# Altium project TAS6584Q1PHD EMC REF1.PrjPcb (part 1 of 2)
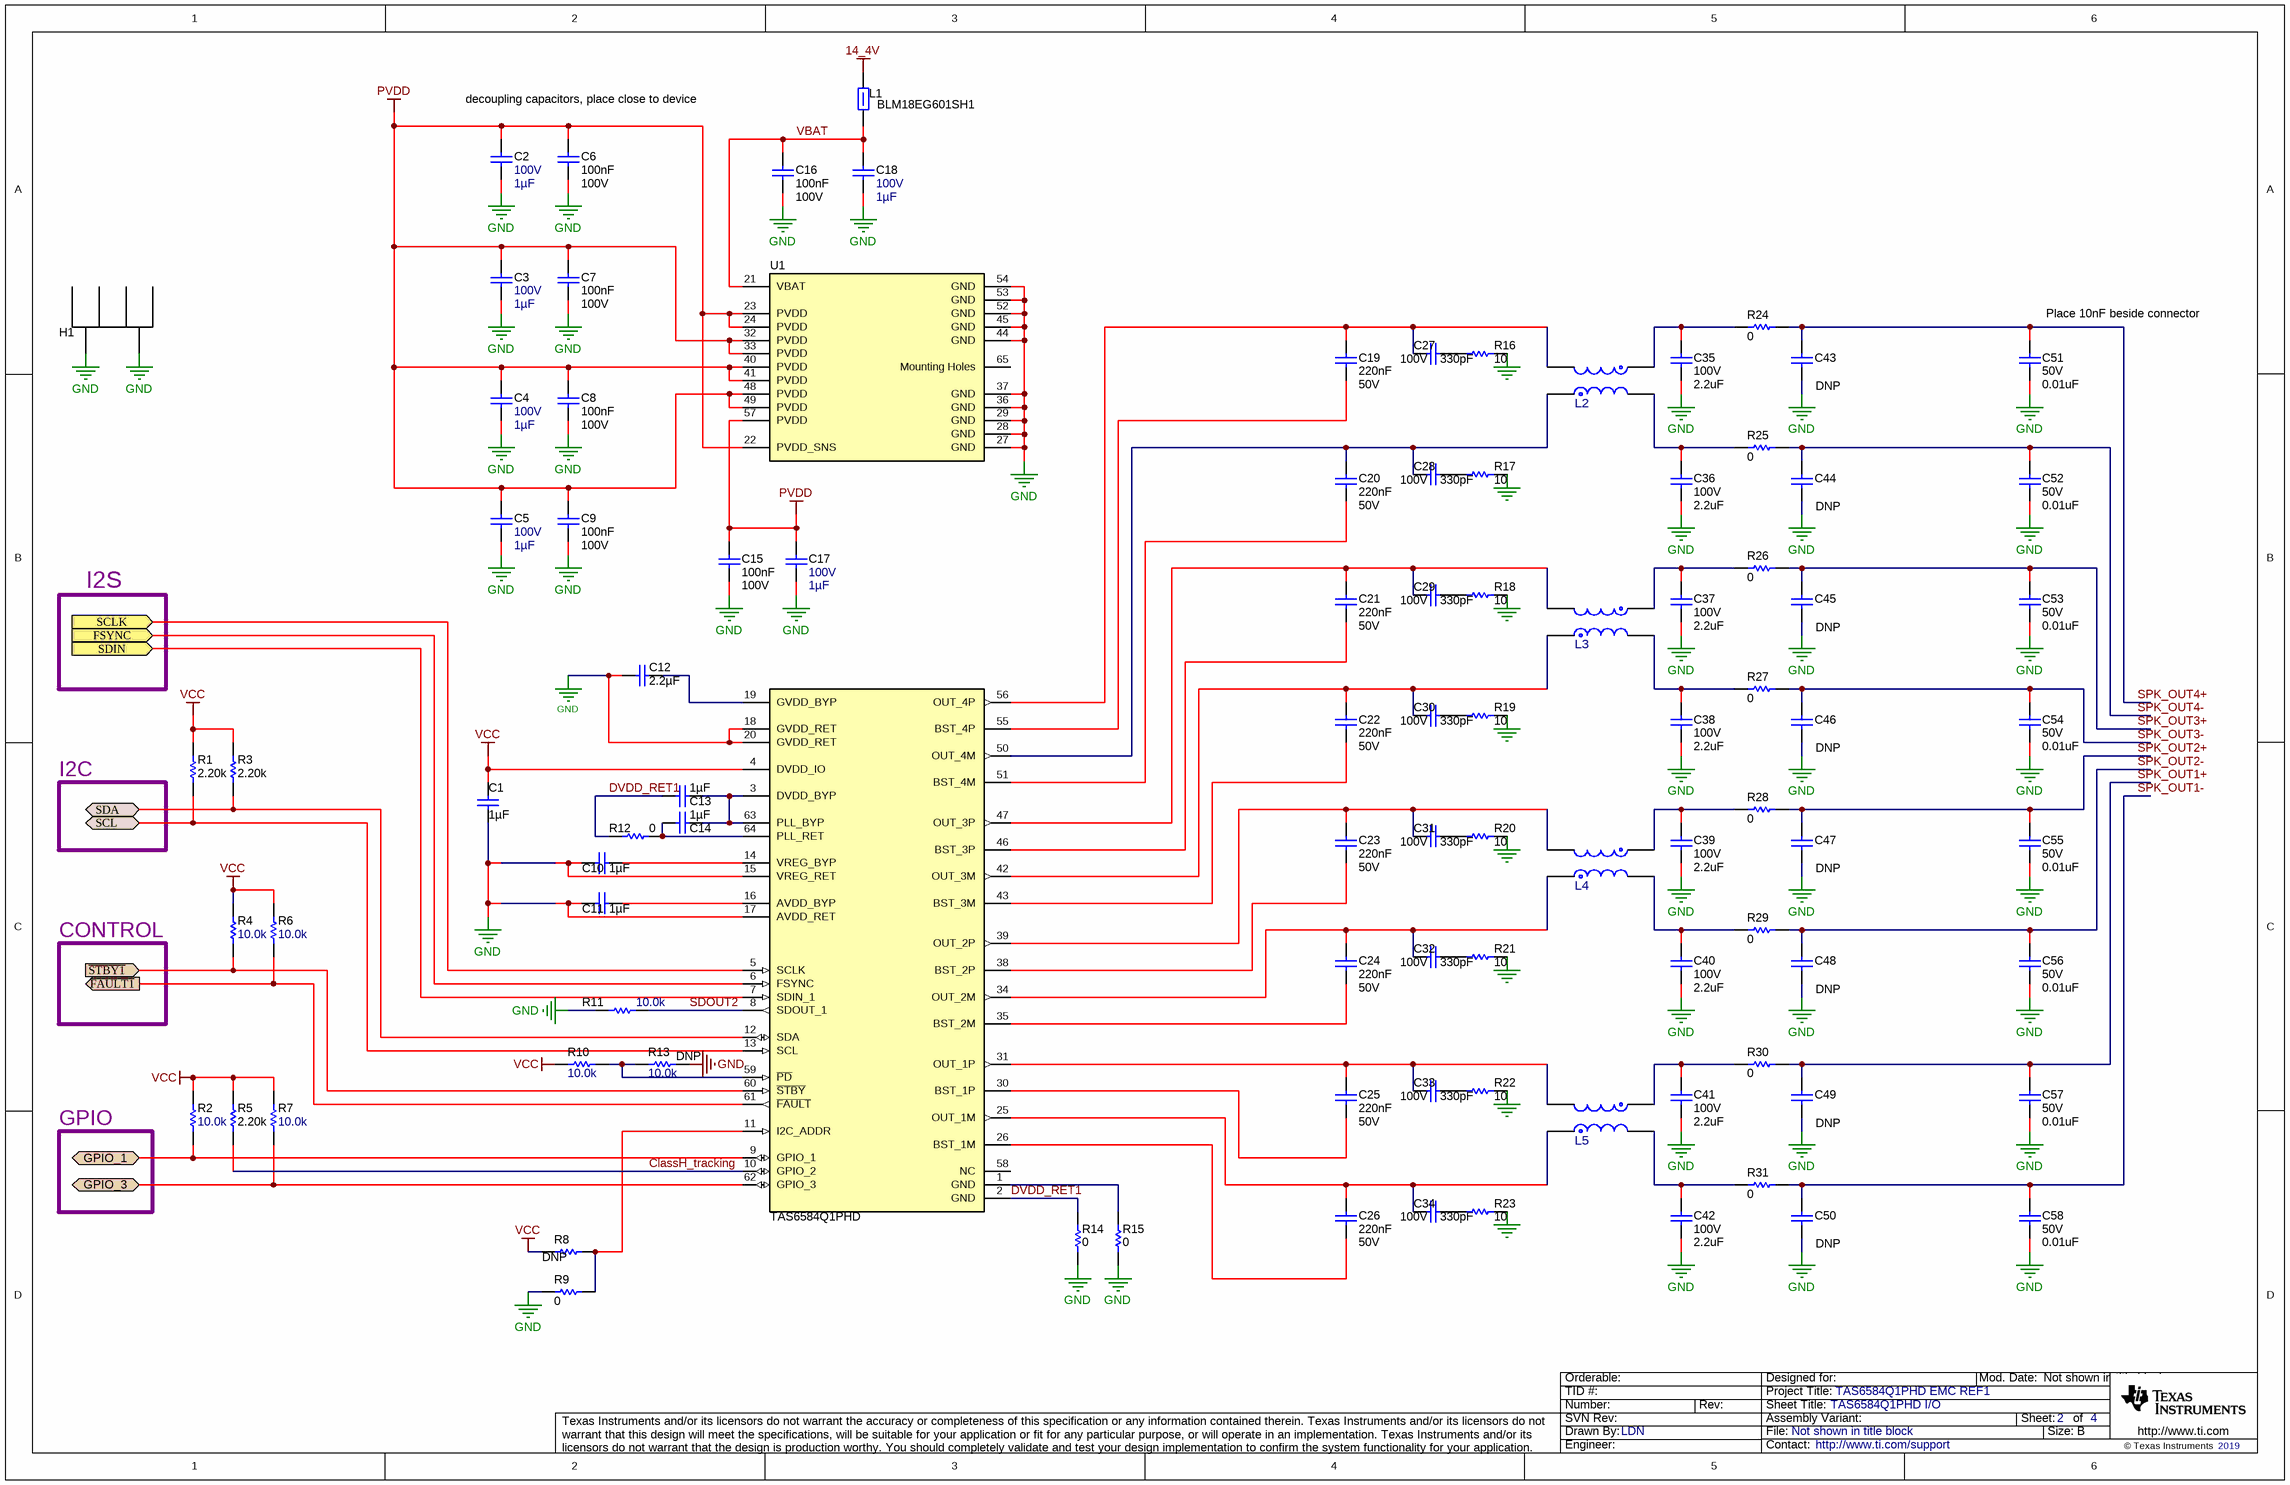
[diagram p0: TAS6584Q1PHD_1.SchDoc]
CopyrightYear: 2019; PRJ_Title: TAS6584Q1PHD EMC REF1; TechSupport: http://www.ti.com/support
7 sheets, 461 parts. Net scope: global (net labels, ports and power ports of the same name join across sheets).
Board file: TAS6584Q1PHD_EMC_0706.PcbDoc
Sheets:
  TAS6584Q1PHD_1.SchDoc
  TAS6584Q1PHD_2.SchDoc
  PowerSupplies_Boostcontroller.SchDoc
  PowerSupplies_Powerstage.SchDoc
  SPDIF and Interface.SchDoc
  ADC.SchDoc
  MCU.SchDoc

## Sheet TAS6584Q1PHD_1.SchDoc: TAS6584Q1PHD I/O
size 431 x 279 mm; Date: Not shown in title block; ApprovedBy: Not shown in title block; CheckedBy: Not shown in title block; Author: Not shown in title block; CompanyName: Not shown in title block; DrawnBy: LDN; Engineer: Not shown in title block; Organization: Not shown in title block; Address1: Not shown in title block; Address2: Not shown in title block; Address3: Not shown in title block; Address4: Not shown in title block; DocumentNumber: 2; Revision: Use project parameter SCH_Rev; SheetNumber: 2; SheetTotal: 4; PageSetup: Record=PageOptions¦CenterHorizontal=True¦CenterVertical=True¦PrintScale=1.00¦XCorrection=1.00¦YCorrection=1.00¦PrintKind=0¦BorderSize=5000000¦LeftOffset=0¦BottomOffset=0¦Orientation=2¦PaperLength=1000¦PaperWidth=1000¦Scale=100¦PaperSource=15¦PrintQuality=600¦MediaType=1¦DitherType=10¦PaperKind=Letter¦PrintScaleMode=1

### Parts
C1  Cap_F: 1µF  [0603L]  (hidden comment: GCM188R71E105KA64D)
C2  VDC_V: 100V  ValueDisplayed: 1µF  [1206L]  (hidden comment: GCJ31CR72A105KA01K)
C3  VDC_V: 100V  ValueDisplayed: 1µF  [1206L]  (hidden comment: GCJ31CR72A105KA01K)
C4  VDC_V: 100V  ValueDisplayed: 1µF  [1206L]  (hidden comment: GCJ31CR72A105KA01K)
C5  VDC_V: 100V  ValueDisplayed: 1µF  [1206L]  (hidden comment: GCJ31CR72A105KA01K)
C6  Cap_F: 100nF  VDC_V: 100V  [0603L]  (hidden comment: GCJ188R72A104KA01D)
C7  Cap_F: 100nF  VDC_V: 100V  [0603L]  (hidden comment: GCJ188R72A104KA01D)
C8  Cap_F: 100nF  VDC_V: 100V  [0603L]  (hidden comment: GCJ188R72A104KA01D)
C9  Cap_F: 100nF  VDC_V: 100V  [0603L]  (hidden comment: GCJ188R72A104KA01D)
C10  Cap_F: 1µF  [0603L]  (hidden comment: GCM188R71E105KA64D)
C11  Cap_F: 1µF  [0603L]  (hidden comment: GCM188R71E105KA64D)
C12  Cap_F: 2.2µF  [0805L]  (hidden comment: GCM21BR71E225KA73L)
C13  Cap_F: 1µF  [0603L]  (hidden comment: GCM188R71E105KA64D)
C14  Cap_F: 1µF  [0603L]  (hidden comment: GCM188R71E105KA64D)
C15  Cap_F: 100nF  VDC_V: 100V  [0603L]  (hidden comment: GCJ188R72A104KA01D)
C16  Cap_F: 100nF  VDC_V: 100V  [0603L]  (hidden comment: GCJ188R72A104KA01D)
C17  VDC_V: 100V  ValueDisplayed: 1µF  [1206L]  (hidden comment: GCJ31CR72A105KA01K)
C18  VDC_V: 100V  ValueDisplayed: 1µF  [1206L]  (hidden comment: GCJ31CR72A105KA01K)
C19  Cap_F: 220nF  VDC_V: 50V  [0603L]  (hidden comment: GCM188R71H224KA64D)
C20  Cap_F: 220nF  VDC_V: 50V  [0603L]  (hidden comment: GCM188R71H224KA64D)
C21  Cap_F: 220nF  VDC_V: 50V  [0603L]  (hidden comment: GCM188R71H224KA64D)
C22  Cap_F: 220nF  VDC_V: 50V  [0603L]  (hidden comment: GCM188R71H224KA64D)
C23  Cap_F: 220nF  VDC_V: 50V  [0603L]  (hidden comment: GCM188R71H224KA64D)
C24  Cap_F: 220nF  VDC_V: 50V  [0603L]  (hidden comment: GCM188R71H224KA64D)
C25  Cap_F: 220nF  VDC_V: 50V  [0603L]  (hidden comment: GCM188R71H224KA64D)
C26  Cap_F: 220nF  VDC_V: 50V  [0603L]  (hidden comment: GCM188R71H224KA64D)
C27  VDC_V: 100V  ValueDisplayed: 330pF  [0402L]  (hidden comment: GRM155R72A331KA01D)
C28  VDC_V: 100V  ValueDisplayed: 330pF  [0402L]  (hidden comment: GRM155R72A331KA01D)
C29  VDC_V: 100V  ValueDisplayed: 330pF  [0402L]  (hidden comment: GRM155R72A331KA01D)
C30  VDC_V: 100V  ValueDisplayed: 330pF  [0402L]  (hidden comment: GRM155R72A331KA01D)
C31  VDC_V: 100V  ValueDisplayed: 330pF  [0402L]  (hidden comment: GRM155R72A331KA01D)
C32  VDC_V: 100V  ValueDisplayed: 330pF  [0402L]  (hidden comment: GRM155R72A331KA01D)
C33  VDC_V: 100V  ValueDisplayed: 330pF  [0402L]  (hidden comment: GRM155R72A331KA01D)
C34  VDC_V: 100V  ValueDisplayed: 330pF  [0402L]  (hidden comment: GRM155R72A331KA01D)
C35  VDC_V: 100V  ValueDisplayed: 2.2uF  [1210_270L]  (hidden comment: GRM32ER72A225KA35L)
C36  VDC_V: 100V  ValueDisplayed: 2.2uF  [1210_270L]  (hidden comment: GRM32ER72A225KA35L)
C37  VDC_V: 100V  ValueDisplayed: 2.2uF  [1210_270L]  (hidden comment: GRM32ER72A225KA35L)
C38  VDC_V: 100V  ValueDisplayed: 2.2uF  [1210_270L]  (hidden comment: GRM32ER72A225KA35L)
C39  VDC_V: 100V  ValueDisplayed: 2.2uF  [1210_270L]  (hidden comment: GRM32ER72A225KA35L)
C40  VDC_V: 100V  ValueDisplayed: 2.2uF  [1210_270L]  (hidden comment: GRM32ER72A225KA35L)
C41  VDC_V: 100V  ValueDisplayed: 2.2uF  [1210_270L]  (hidden comment: GRM32ER72A225KA35L)
C42  VDC_V: 100V  ValueDisplayed: 2.2uF  [1210_270L]  (hidden comment: GRM32ER72A225KA35L)
C43  DNP  [0805_HV]
C44  DNP  [0805_HV]
C45  DNP  [0805_HV]
C46  DNP  [0805_HV]
C47  DNP  [0805_HV]
C48  DNP  [0805_HV]
C49  DNP  [0805_HV]
C50  DNP  [0805_HV]
C51  VDC_V: 50V  ValueDisplayed: 0.01uF  [0603L]  (hidden comment: GRM1885C1H103JA01D)
C52  VDC_V: 50V  ValueDisplayed: 0.01uF  [0603L]  (hidden comment: GRM1885C1H103JA01D)
C53  VDC_V: 50V  ValueDisplayed: 0.01uF  [0603L]  (hidden comment: GRM1885C1H103JA01D)
C54  VDC_V: 50V  ValueDisplayed: 0.01uF  [0603L]  (hidden comment: GRM1885C1H103JA01D)
C55  VDC_V: 50V  ValueDisplayed: 0.01uF  [0603L]  (hidden comment: GRM1885C1H103JA01D)
C56  VDC_V: 50V  ValueDisplayed: 0.01uF  [0603L]  (hidden comment: GRM1885C1H103JA01D)
C57  VDC_V: 50V  ValueDisplayed: 0.01uF  [0603L]  (hidden comment: GRM1885C1H103JA01D)
C58  VDC_V: 50V  ValueDisplayed: 0.01uF  [0603L]  (hidden comment: GRM1885C1H103JA01D)
H1  Used in BOM report  [Heatsink_TAS65xx_EMI]  (value not drawn)
L1  BLM18EG601SH1  [0603L]
L2  VAMV1009AA-100MM2  [FP-VAMV1009AA-100MM2_SMT_CMC_9MM2_10MM2-MFG]  (value not drawn)
L3  VAMV1009AA-100MM2  [FP-VAMV1009AA-100MM2_SMT_CMC_9MM2_10MM2-MFG]  (value not drawn)
L4  VAMV1009AA-100MM2  [FP-VAMV1009AA-100MM2_SMT_CMC_9MM2_10MM2-MFG]  (value not drawn)
L5  VAMV1009AA-100MM2  [FP-VAMV1009AA-100MM2_SMT_CMC_9MM2_10MM2-MFG]  (value not drawn)
R1  ValueDisplayed: 2.20k  [0402L]  (hidden comment: CRCW04022K20FKED)
R2  ValueDisplayed: 10.0k  [0402L]  (hidden comment: CMP-0025958-3)
R3  ValueDisplayed: 2.20k  [0402L]  (hidden comment: CRCW04022K20FKED)
R4  ValueDisplayed: 10.0k  [0402L]  (hidden comment: CMP-0025958-3)
R5  ValueDisplayed: 2.20k  [0402L]  (hidden comment: CRCW04022K20FKED)
R6  ValueDisplayed: 10.0k  [0402L]  (hidden comment: CMP-0025958-3)
R7  ValueDisplayed: 10.0k  [0402L]  (hidden comment: CMP-0025958-3)
R8  DNP  [0402L]
R9  ValueDisplayed: 0  [0402L]  (hidden comment: CRCW04020000Z0ED)
R10  ValueDisplayed: 10.0k  [0402L]  (hidden comment: CMP-0025958-3)
R11  ValueDisplayed: 10.0k  [0402L]  (hidden comment: CMP-0025958-3)
R12  ValueDisplayed: 0  [0402L]  (hidden comment: CRCW04020000Z0ED)
R13  DNP  ValueDisplayed: 10.0k  [0402L]
R14  ValueDisplayed: 0  [0402L]  (hidden comment: CRCW04020000Z0ED)
R15  ValueDisplayed: 0  [0402L]  (hidden comment: CRCW04020000Z0ED)
R16  ValueDisplayed: 10  [0805_HV]  (hidden comment: CRCW080510R0JNEA)
R17  ValueDisplayed: 10  [0805_HV]  (hidden comment: CRCW080510R0JNEA)
R18  ValueDisplayed: 10  [0805_HV]  (hidden comment: CRCW080510R0JNEA)
R19  ValueDisplayed: 10  [0805_HV]  (hidden comment: CRCW080510R0JNEA)
R20  ValueDisplayed: 10  [0805_HV]  (hidden comment: CRCW080510R0JNEA)
R21  ValueDisplayed: 10  [0805_HV]  (hidden comment: CRCW080510R0JNEA)
R22  ValueDisplayed: 10  [0805_HV]  (hidden comment: CRCW080510R0JNEA)
R23  ValueDisplayed: 10  [0805_HV]  (hidden comment: CRCW080510R0JNEA)
R24  ValueDisplayed: 0  [1210]  (hidden comment: MCR25JZHJ000)
R25  ValueDisplayed: 0  [1210]  (hidden comment: MCR25JZHJ000)
R26  ValueDisplayed: 0  [1210]  (hidden comment: MCR25JZHJ000)
R27  ValueDisplayed: 0  [1210]  (hidden comment: MCR25JZHJ000)
R28  ValueDisplayed: 0  [1210]  (hidden comment: MCR25JZHJ000)
R29  ValueDisplayed: 0  [1210]  (hidden comment: MCR25JZHJ000)
R30  ValueDisplayed: 0  [1210]  (hidden comment: MCR25JZHJ000)
R31  ValueDisplayed: 0  [1210]  (hidden comment: MCR25JZHJ000)
U1  TAS6584Q1PHD  [QFP64-PHD]

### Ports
FSYNC (in), GPIO_1 (bidir), GPIO_3 (bidir), SCL (bidir), SCLK (in), SDA (bidir), SDIN (in), ~{FAULT1} (out), ~{STBY1} (in)

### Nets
14_4V: L1.2
GND: C1.2 C2.2 C3.2 C4.2 C5.2 C6.2 C7.2 C8.2 C9.2 C10.1 C11.1 C12.2 C15.2 C16.2 C17.2 C18.2 C35.2 C36.2 C37.2 C38.2 C39.2 C40.2 C41.2 C42.2 C43.2 C44.2 C45.2 C46.2 C47.2 C48.2 C49.2 C50.2 C51.2 C52.2 C53.2 C54.2 C55.2 C56.2 C57.2 C58.2 H1.1 H1.2 R9.2 R11.2 R13.1 R14.2 R15.2 R16.2 R17.2 R18.2 R19.2 R20.2 R21.2 R22.2 R23.2 U1.15(VREG_RET) U1.17(AVDD_RET) U1.18(GVDD_RET) U1.20(GVDD_RET) U1.27(GND) U1.28(GND) U1.29(GND) U1.36(GND) U1.37(GND) U1.44(GND) U1.45(GND) U1.52(GND) U1.53(GND) U1.54(GND)
PVDD: C2.1 C3.1 C4.1 C5.1 C6.1 C7.1 C8.1 C9.1 C15.1 C17.1 U1.22(PVDD_SNS) U1.23(PVDD) U1.24(PVDD) U1.32(PVDD) U1.33(PVDD) U1.40(PVDD) U1.41(PVDD) U1.48(PVDD) U1.49(PVDD) U1.57(PVDD)
VCC: C1.1 R1.2 R2.2 R3.2 R4.2 R5.2 R6.2 R7.2 R8.2 R10.2 U1.4(DVDD_IO)
~{FAULT1}: R6.1 U1.61(~{FAULT}) ; port ~{FAULT1}
~{STBY1}: R4.1 U1.60(~{STBY}) ; port ~{STBY1}
ClassH_tracking: R5.1 U1.10(GPIO_2)
DVDD_RET1: C13.1 R12.2 R14.1 U1.2(GND)
GPIO_1: R2.1 U1.9(GPIO_1) ; port GPIO_1
GPIO_3: R7.1 U1.62(GPIO_3) ; port GPIO_3
LRCLK: U1.6(FSYNC) ; port FSYNC
SCL: R1.1 U1.13(SCL) ; port SCL
SCLK: U1.5(SCLK) ; port SCLK
SDA: R3.1 U1.12(SDA) ; port SDA
SDIN: U1.7(SDIN_1) ; port SDIN
SDOUT2: R11.1 U1.8(SDOUT_1)
SPK_OUT1+: C49.1 C57.1 R30.2
SPK_OUT1-: C50.1 C58.1 R31.2
SPK_OUT2+: C47.1 C55.1 R28.2
SPK_OUT2-: C48.1 C56.1 R29.2
SPK_OUT3+: C45.1 C53.1 R26.2
SPK_OUT3-: C46.1 C54.1 R27.2
SPK_OUT4+: C43.1 C51.1 R24.2
SPK_OUT4-: C44.1 C52.1 R25.2
VBAT: C16.1 C18.1 L1.1 U1.21(VBAT)
NetC10_2: C10.2 U1.14(VREG_BYP)
NetC11_2: C11.2 U1.16(AVDD_BYP)
NetC12_1: C12.1 U1.19(GVDD_BYP)
NetC13_2: C13.2 C14.2 U1.3(DVDD_BYP) U1.63(PLL_BYP)
NetC14_1: C14.1 R12.1 U1.64(PLL_RET)
NetC19_1: C19.1 C27.2 L2.4(2_Finish) U1.56(OUT_4P)
NetC19_2: C19.2 U1.55(BST_4P)
NetC20_1: C20.1 C28.2 L2.1(1_Start) U1.50(OUT_4M)
NetC20_2: C20.2 U1.51(BST_4M)
NetC21_1: C21.1 C29.2 L3.4(2_Finish) U1.47(OUT_3P)
NetC21_2: C21.2 U1.46(BST_3P)
NetC22_1: C22.1 C30.2 L3.1(1_Start) U1.42(OUT_3M)
NetC22_2: C22.2 U1.43(BST_3M)
NetC23_1: C23.1 C31.2 L4.4(2_Finish) U1.39(OUT_2P)
NetC23_2: C23.2 U1.38(BST_2P)
NetC24_1: C24.1 C32.2 L4.1(1_Start) U1.34(OUT_2M)
NetC24_2: C24.2 U1.35(BST_2M)
NetC25_1: C25.1 C33.2 L5.4(2_Finish) U1.31(OUT_1P)
NetC25_2: C25.2 U1.30(BST_1P)
NetC26_1: C26.1 C34.2 L5.1(1_Start) U1.25(OUT_1M)
NetC26_2: C26.2 U1.26(BST_1M)
NetC27_1: C27.1 R16.1
NetC28_1: C28.1 R17.1
NetC29_1: C29.1 R18.1
NetC30_1: C30.1 R19.1
NetC31_1: C31.1 R20.1
NetC32_1: C32.1 R21.1
NetC33_1: C33.1 R22.1
NetC34_1: C34.1 R23.1
NetC35_1: C35.1 L2.3(2_Start) R24.1
NetC36_1: C36.1 L2.2(1_Finish) R25.1
NetC37_1: C37.1 L3.3(2_Start) R26.1
NetC38_1: C38.1 L3.2(1_Finish) R27.1
NetC39_1: C39.1 L4.3(2_Start) R28.1
NetC40_1: C40.1 L4.2(1_Finish) R29.1
NetC41_1: C41.1 L5.3(2_Start) R30.1
NetC42_1: C42.1 L5.2(1_Finish) R31.1
NetR8_1: R8.1 R9.1 U1.11(I2C_ADDR)
NetR10_1: R10.1 R13.2 U1.59(~{PD})
NetR15_1: R15.1 U1.1(GND)

Not connected (* = marked no-connect by the designer): U1 58(NC) 65(Mounting_Holes)

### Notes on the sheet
- decoupling capacitors, place close to device
- (near C51) Place 10nF beside connector
- I2S
- I2C
- CONTROL
- GPIO

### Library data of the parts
C1 C10 C11 C13 C14 = CMP-0007139-1: CAP, CERM, 1 uF, 25 V, +/- 10%, X7R, AEC-Q200 Grade 1, 0603; Manufacturer: MuRata; TaMin_C: -55°C; Polarized: N; SizeAreaWB_mm2: 4.68; Value1: Unknown; U/M: EA; Value: 1uF; TaMax_C: 125°C; SizeZ_mm: 1; SizeX_mm: 1.6; SizeY_mm: 0.8; Cap_Case: 0603; Value2: 25V; SizeArea_mm2: 1.28; AEC Qualified: Y; AEC Category: Q200
C2-C5 C17 C18 = CMP-0750040-1: CAP, CERM, 1 µF, 100 V,+/- 10%, X7R, AEC-Q200 Grade 1, 1206; Manufacturer: MuRata; Value: 1uF; U/M: EA; SizeX_mm: 3.2; Polarized: N; TaMin_C: -55°C; SizeZ_mm: 1.35; SizeY_mm: 1.6; AEC Category: Q200; SizeArea_mm2: 5.12; TaMax_C: 125°C; Cap_Case: 1206; AEC Grade: 1; AEC Qualified: Y; SizeAreaWB_mm2: 10.92
C6-C9 C15 C16 = CMP-0064935-4: CAP, CERM, 0.1 uF, 100 V,+/- 10%, X7R, AEC-Q200 Grade 1, 0603; Manufacturer: MuRata; TaMin_C: -55°C; Polarized: N; SizeAreaWB_mm2: 4.68; Value1: Unknown; U/M: EA; Value: 0.1uF; TaMax_C: 125°C; SizeZ_mm: 1; SizeX_mm: 1.6; SizeY_mm: 0.8; Cap_Case: 0603; SizeArea_mm2: 1.28; AEC Qualified: Y; AEC Category: Q200
C12 = CMP-0083622-1: CAP, CERM, 2.2 µF, 25 V,+/- 10%, X7R, AEC-Q200 Grade 1, 0805; Manufacturer: MuRata; TaMin_C: -55°C; Polarized: N; SizeAreaWB_mm2: 6.75; U/M: EA; Value: 2.2uF; TaMax_C: 125°C; SizeZ_mm: 1.45; SizeX_mm: 2; SizeY_mm: 1.25; Cap_Case: 0805; Value2: 25V; SizeArea_mm2: 2.5; AEC Qualified: Y; AEC Grade: 1; AEC Category: Q200
C19-C26 = CMP-0007145-1: CAP, CERM, 0.22 uF, 50 V, +/- 10%, X7R, AEC-Q200 Grade 1, 0603; Manufacturer: MuRata; TaMin_C: -55°C; Polarized: N; SizeAreaWB_mm2: 4.68; Value1: Unknown; U/M: EA; Value: 0.22uF; TaMax_C: 125°C; SizeZ_mm: 1; SizeX_mm: 1.6; SizeY_mm: 0.8; Cap_Case: 0603; SizeArea_mm2: 1.28; AEC Qualified: Y; AEC Category: Q200
C27-C34 = CMP-0006707-2: CAP, CERM, 330 pF, 100 V, +/- 10%, X7R, 0402; Manufacturer: MuRata; TaMin_C: -55°C; Polarized: N; SizeAreaWB_mm2: 3; Value1: Unknown; U/M: EA; Value: 330pF; TaMax_C: 125°C; SizeZ_mm: 0.6; SizeX_mm: 1; SizeY_mm: 0.5; Cap_Case: 0402; AEC Category: Q200
C35-C42 = CMP-0009232-1: CAP, CERM, 2.2 uF, 100 V, +/- 10%, X7R, 1210; Manufacturer: MuRata; TaMin_C: -55°C; ESR_ohm: 7m; Polarized: N; SizeAreaWB_mm2: 14.7; Value1: 0.007 ohm; U/M: EA; Value: 2.2uF; TaMax_C: 125°C; SizeZ_mm: 2.7; SizeX_mm: 3.2; SizeY_mm: 2.5; Cap_Case: 1210; SizeArea_mm2: 8; Cap_F: 2.2µF; IRMS_A: 4.4A; AEC Category: Q200
C43-C50 = CMP-0008022-1: CAP, CERM, 0.47 uF, 50 V, +/- 10%, X7R, AEC-Q200 Grade 1, 0805; Manufacturer: MuRata; PartNumber: GCM21BR71H474KA55L; TaMin_C: -55°C; Polarized: N; SizeAreaWB_mm2: 6.75; Value1: Unknown; U/M: EA; Value: 0.47uF; TaMax_C: 125°C; SizeZ_mm: 1.45; SizeX_mm: 2; SizeY_mm: 1.25; Cap_Case: 0805; Value2: 50V; SizeArea_mm2: 2.5; AEC Qualified: Y; Cap_F: 470nF; AEC Grade: 1; AEC Category: Q200
C51-C58 = CMP-0007174-3: CAP, CERM, 0.01 uF, 50 V, +/- 5%, C0G/NP0, 0603; Manufacturer: MuRata; TaMin_C: -55°C; Polarized: N; SizeAreaWB_mm2: 4.68; Value1: Unknown; U/M: EA; Value: 0.01uF; TaMax_C: 125°C; SizeZ_mm: 1; SizeX_mm: 1.6; SizeY_mm: 0.8; Cap_Case: 0603; SizeArea_mm2: 1.28; Cap_F: 10nF; AEC Category: Q200
H1 = Heatsink: TAS6584 EMI board heatsink; CompType: Used in some BOM reports.  Useful for finding later.
L1 = CMP-0003347-2: Ferrite Bead, 600 ohm @ 100 MHz, 0.5 A, 0603; Manufacturer: MuRata; Ztyp@1GHz_Ohm: 700; ZTyp@100MHz_Ohm: 600; SizeAreaWB_mm2: 4.68; DCR_ohm: 0.35; Value1: 0.35 ohm; Value: 600 ohm; Imax_A: 500mA; SizeZ_mm: 1; SizeX_mm: 1.6; SizeY_mm: 0.8; Value2: 0.5A; SizeArea_mm2: 1.28
L2-L5 = CMP-0093075-1: Power Choke Coil, 10uH 20% 100kHz, 22mΩ DCR max, Idc 5.8A, Isat 10A; Manufacturer: Cyntec; SizeZ_mm: 11.05mm; AEC Grade: Grade 1; DCR_ohm: 22m; Ind_H: 10µH; AEC Qualified: Yes; Material: Metal Dust
R1 R3 R5 = CMP-0026231-2: RES, 2.20 k, 1%, 0.063 W, AEC-Q200 Grade 0, 0402; Manufacturer: Vishay-Dale; Power_W: 63mW; TempCo: 100 ppm/C; Value_Code: 2k20; Value: 2.20k; Res_ohm: 2.2k; SizeX_mm: 1; SizeY_mm: 0.5; SizeZ_mm: 0.6; Value2: 0.063W; AEC Qualified: Y; AEC Category: Q200; AEC Grade: 0
R2 R4 R6 R7 R10 R11 R13 = CMP-0025958-3: RES, 10.0 k, 1%, 0.063 W, AEC-Q200 Grade 0, 0402; PartNumber: CRCW040210K0FKED; Manufacturer: Vishay-Dale; Value: 10.0k; Res_ohm: 10k; Value_Code: 10k0; Power_W: 63mW; Value2: 0.063W; VDC_V: 50V; TempCo: 100 ppm/C; EIA_Code: E96; SizeX_mm: 1; SizeY_mm: 0.5; SizeZ_mm: 0.6; AEC Qualified: Y; AEC Category: Q200; AEC Grade: 0
R8 = CMP-0026822-3: RES, 0, 5%, 0.063 W, AEC-Q200 Grade 0, 0402; Manufacturer: Vishay-Dale; PartNumber: CRCW04020000Z0ED; Power_W: 63mW; TempCo: 200 ppm/C; Value_Code: 0000; Value: 0; EIA_Code: E24; SizeX_mm: 1; SizeY_mm: 0.5; SizeZ_mm: 0.6; Value2: 0.063W; AEC Qualified: Y; VDC_V: 50V; AEC Category: Q200
R9 R12 R14 R15 = CMP-0026822-3: RES, 0, 5%, 0.063 W, AEC-Q200 Grade 0, 0402; Manufacturer: Vishay-Dale; Power_W: 63mW; TempCo: 200 ppm/C; Value_Code: 0000; Value: 0; EIA_Code: E24; SizeX_mm: 1; SizeY_mm: 0.5; SizeZ_mm: 0.6; Value2: 0.063W; AEC Qualified: Y; VDC_V: 50V; AEC Category: Q200
R16-R23 = CMP-0020448-3: RES, 10, 5%, 0.125 W, AEC-Q200 Grade 0, 0805; Manufacturer: Vishay-Dale; Power_W: 125mW; TempCo: 200 ppm/C; Value_Code: 10R0; Value: 10; EIA_Code: E24; SizeX_mm: 2; SizeY_mm: 1.25; SizeZ_mm: 1.45; Value2: 0.125W; SizeArea_mm2: 2.5; AEC Qualified: Y; VDC_V: 150V; AEC Category: Q200; AEC Grade: 0
R24-R31 = CMP-0015361-2: RES, 0, 5%, 0.25 W, 1210; Manufacturer: Rohm; Power_W: 250mW; TempCo: 20 ppm/C; SizeAreaWB_mm2: 14.7; Value_Code: 0000; U/M: EA; Value: 0; EIA_Code: E24; SizeX_mm: 3.2; SizeY_mm: 2.5; SizeZ_mm: 1.35; Value2: 0.25W; SizeArea_mm2: 8; VDC_V: 200V; AEC Category: Q200
U1 = TAS6584Q1PHD: 20W Inductor-Less, Digital Input, Stereo, Closed-Loop Class-D Audio Amplifier with Enhanced Processing and and DirectPath HP Driver (DCP0038); Manufacturer: Texas Instruments; SymbolCreator: Altium; CompType: IC; U/M: EA

## Sheet TAS6584Q1PHD_2.SchDoc: TAS6584Q1PHD I/O
size 431 x 279 mm; Date: Not shown in title block; ApprovedBy: Not shown in title block; CheckedBy: Not shown in title block; Author: Not shown in title block; CompanyName: Not shown in title block; DrawnBy: LDN; Engineer: Not shown in title block; Organization: Not shown in title block; Address1: Not shown in title block; Address2: Not shown in title block; Address3: Not shown in title block; Address4: Not shown in title block; DocumentNumber: 2; Revision: Use project parameter SCH_Rev; SheetNumber: 2; SheetTotal: 4; PageSetup: Record=PageOptions¦CenterHorizontal=True¦CenterVertical=True¦PrintScale=1.00¦XCorrection=1.00¦YCorrection=1.00¦PrintKind=0¦BorderSize=5000000¦LeftOffset=0¦BottomOffset=0¦Orientation=2¦PaperLength=1000¦PaperWidth=1000¦Scale=100¦PaperSource=15¦PrintQuality=600¦MediaType=1¦DitherType=10¦PaperKind=Letter¦PrintScaleMode=1
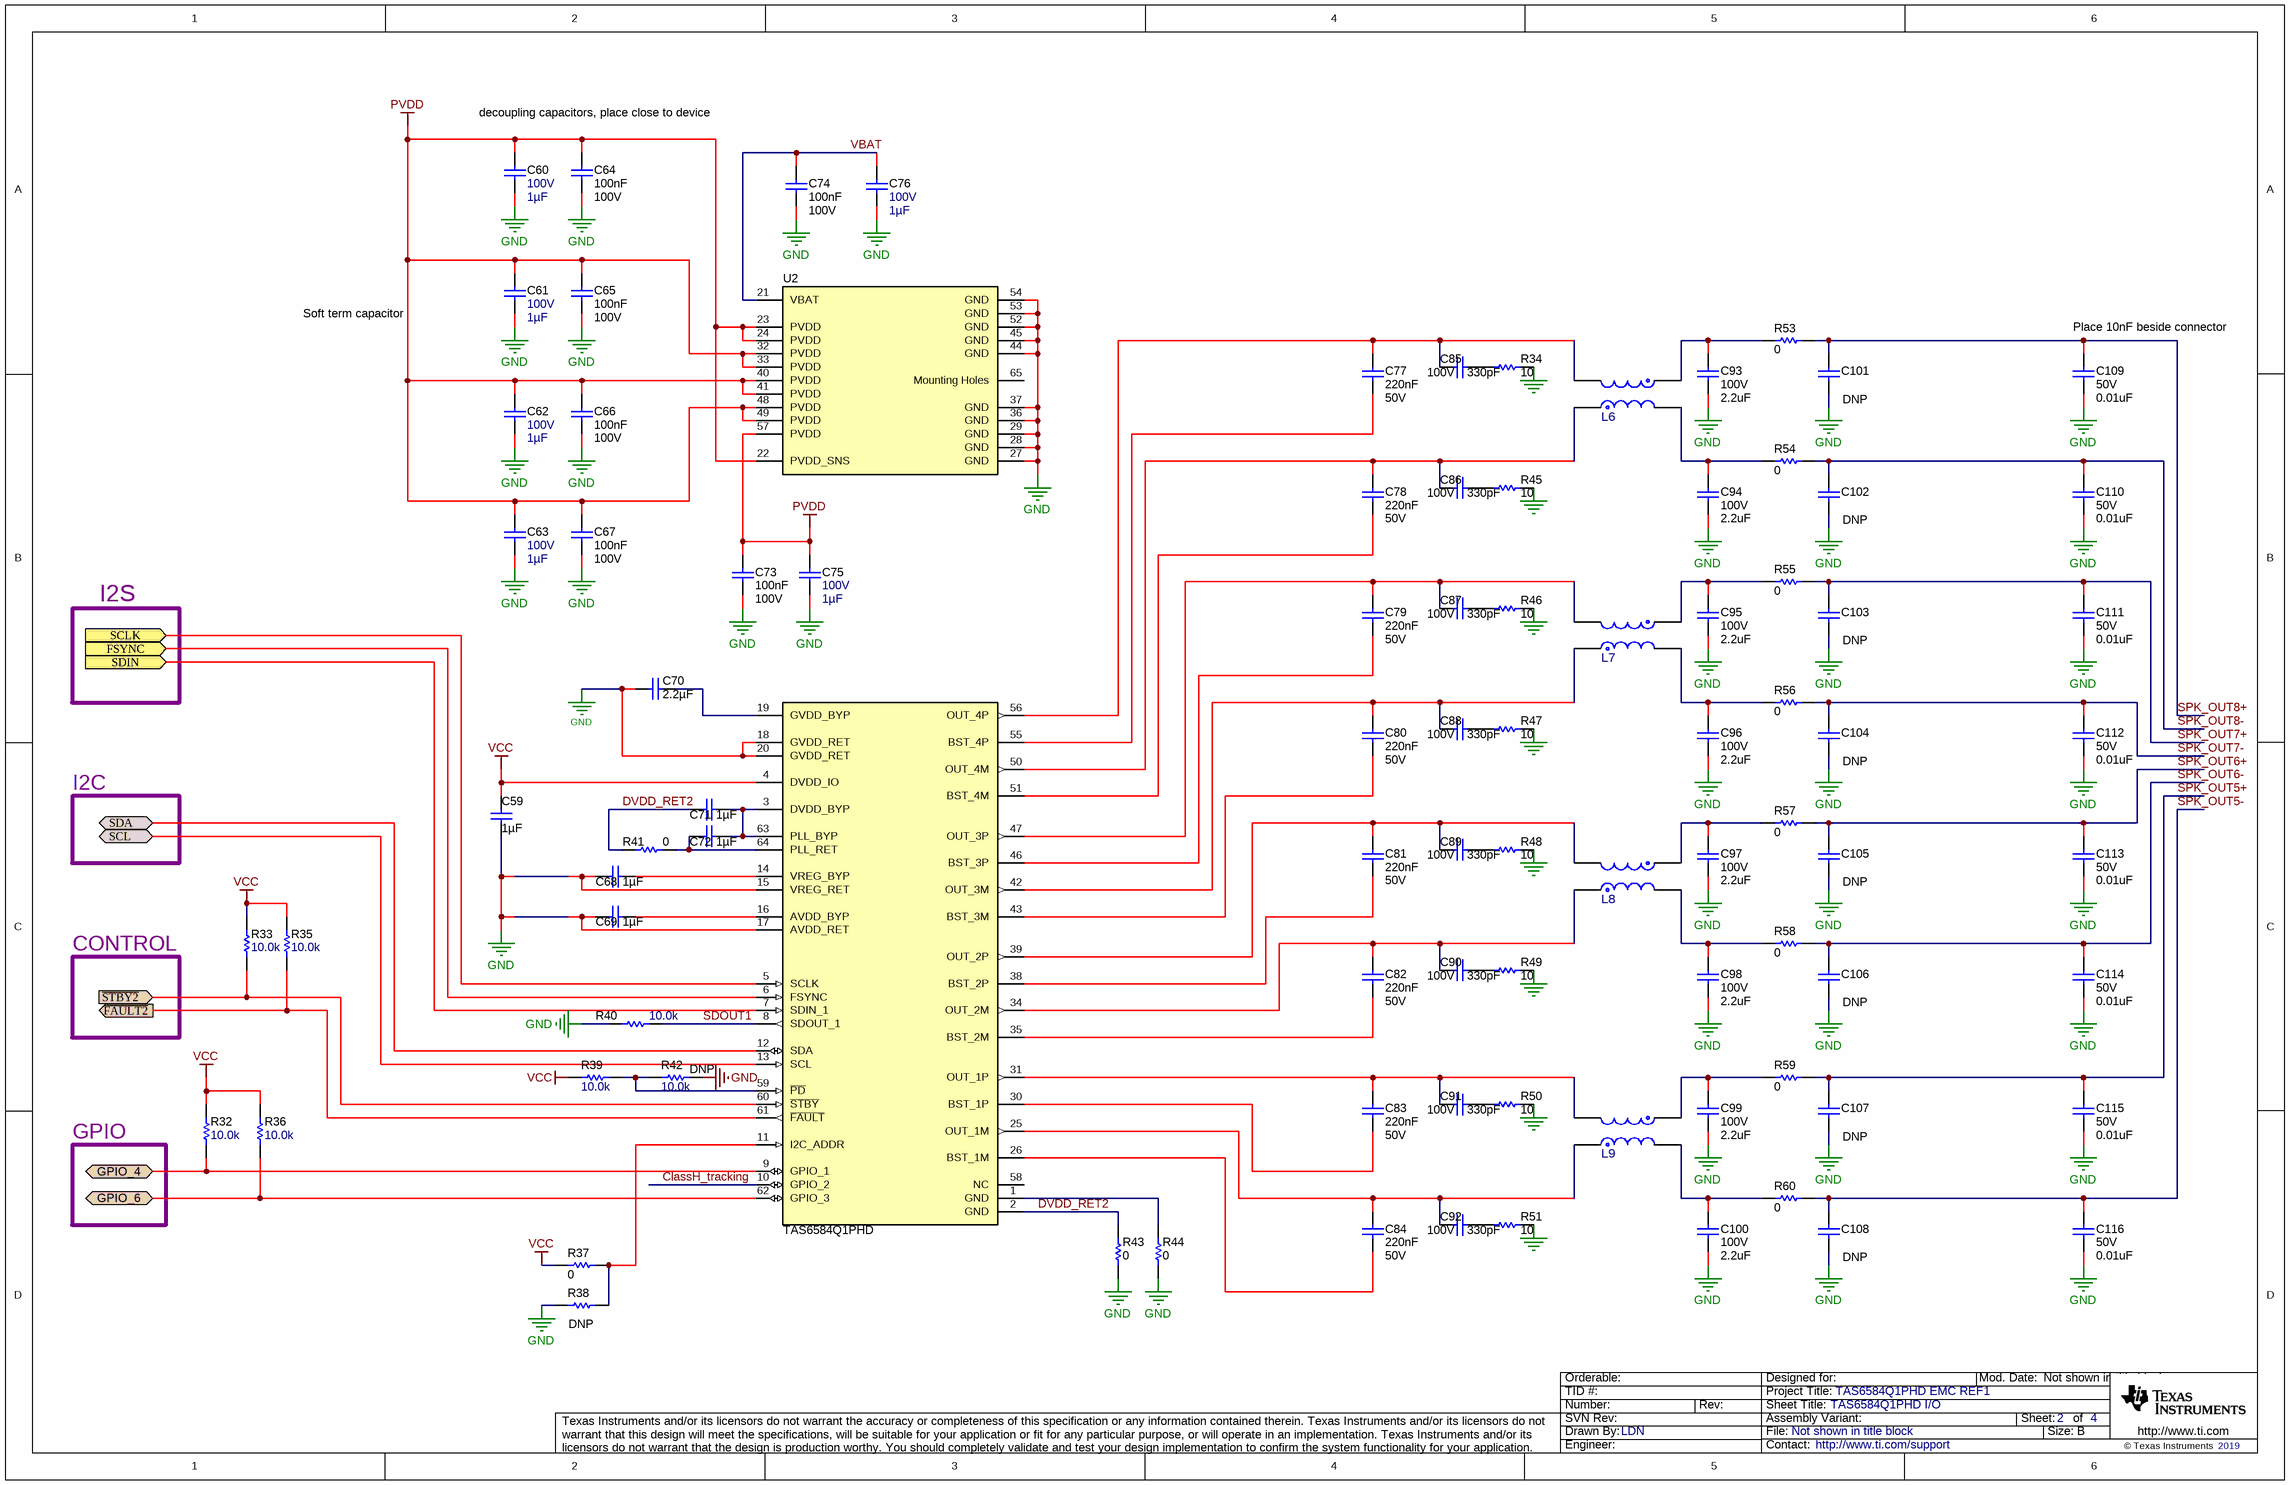
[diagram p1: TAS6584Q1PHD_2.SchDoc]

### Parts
C59  Cap_F: 1µF  [0603L]  (hidden comment: GCM188R71E105KA64D)
C60  VDC_V: 100V  ValueDisplayed: 1µF  [1206L]  (hidden comment: GCJ31CR72A105KA01K)
C61  VDC_V: 100V  ValueDisplayed: 1µF  [1206L]  (hidden comment: GCJ31CR72A105KA01K)
C62  VDC_V: 100V  ValueDisplayed: 1µF  [1206L]  (hidden comment: GCJ31CR72A105KA01K)
C63  VDC_V: 100V  ValueDisplayed: 1µF  [1206L]  (hidden comment: GCJ31CR72A105KA01K)
C64  Cap_F: 100nF  VDC_V: 100V  [0603L]  (hidden comment: GCJ188R72A104KA01D)
C65  Cap_F: 100nF  VDC_V: 100V  [0603L]  (hidden comment: GCJ188R72A104KA01D)
C66  Cap_F: 100nF  VDC_V: 100V  [0603L]  (hidden comment: GCJ188R72A104KA01D)
C67  Cap_F: 100nF  VDC_V: 100V  [0603L]  (hidden comment: GCJ188R72A104KA01D)
C68  Cap_F: 1µF  [0603L]  (hidden comment: GCM188R71E105KA64D)
C69  Cap_F: 1µF  [0603L]  (hidden comment: GCM188R71E105KA64D)
C70  Cap_F: 2.2µF  [0805L]  (hidden comment: GCM21BR71E225KA73L)
C71  Cap_F: 1µF  [0603L]  (hidden comment: GCM188R71E105KA64D)
C72  Cap_F: 1µF  [0603L]  (hidden comment: GCM188R71E105KA64D)
C73  Cap_F: 100nF  VDC_V: 100V  [0603L]  (hidden comment: GCJ188R72A104KA01D)
C74  Cap_F: 100nF  VDC_V: 100V  [0603L]  (hidden comment: GCJ188R72A104KA01D)
C75  VDC_V: 100V  ValueDisplayed: 1µF  [1206L]  (hidden comment: GCJ31CR72A105KA01K)
C76  VDC_V: 100V  ValueDisplayed: 1µF  [1206L]  (hidden comment: GCJ31CR72A105KA01K)
C77  Cap_F: 220nF  VDC_V: 50V  [0603L]  (hidden comment: GCM188R71H224KA64D)
C78  Cap_F: 220nF  VDC_V: 50V  [0603L]  (hidden comment: GCM188R71H224KA64D)
C79  Cap_F: 220nF  VDC_V: 50V  [0603L]  (hidden comment: GCM188R71H224KA64D)
C80  Cap_F: 220nF  VDC_V: 50V  [0603L]  (hidden comment: GCM188R71H224KA64D)
C81  Cap_F: 220nF  VDC_V: 50V  [0603L]  (hidden comment: GCM188R71H224KA64D)
C82  Cap_F: 220nF  VDC_V: 50V  [0603L]  (hidden comment: GCM188R71H224KA64D)
C83  Cap_F: 220nF  VDC_V: 50V  [0603L]  (hidden comment: GCM188R71H224KA64D)
C84  Cap_F: 220nF  VDC_V: 50V  [0603L]  (hidden comment: GCM188R71H224KA64D)
C85  VDC_V: 100V  ValueDisplayed: 330pF  [0402L]  (hidden comment: GRM155R72A331KA01D)
C86  VDC_V: 100V  ValueDisplayed: 330pF  [0402L]  (hidden comment: GRM155R72A331KA01D)
C87  VDC_V: 100V  ValueDisplayed: 330pF  [0402L]  (hidden comment: GRM155R72A331KA01D)
C88  VDC_V: 100V  ValueDisplayed: 330pF  [0402L]  (hidden comment: GRM155R72A331KA01D)
C89  VDC_V: 100V  ValueDisplayed: 330pF  [0402L]  (hidden comment: GRM155R72A331KA01D)
C90  VDC_V: 100V  ValueDisplayed: 330pF  [0402L]  (hidden comment: GRM155R72A331KA01D)
C91  VDC_V: 100V  ValueDisplayed: 330pF  [0402L]  (hidden comment: GRM155R72A331KA01D)
C92  VDC_V: 100V  ValueDisplayed: 330pF  [0402L]  (hidden comment: GRM155R72A331KA01D)
C93  VDC_V: 100V  ValueDisplayed: 2.2uF  [1210_270L]  (hidden comment: GRM32ER72A225KA35L)
C94  VDC_V: 100V  ValueDisplayed: 2.2uF  [1210_270L]  (hidden comment: GRM32ER72A225KA35L)
C95  VDC_V: 100V  ValueDisplayed: 2.2uF  [1210_270L]  (hidden comment: GRM32ER72A225KA35L)
C96  VDC_V: 100V  ValueDisplayed: 2.2uF  [1210_270L]  (hidden comment: GRM32ER72A225KA35L)
C97  VDC_V: 100V  ValueDisplayed: 2.2uF  [1210_270L]  (hidden comment: GRM32ER72A225KA35L)
C98  VDC_V: 100V  ValueDisplayed: 2.2uF  [1210_270L]  (hidden comment: GRM32ER72A225KA35L)
C99  VDC_V: 100V  ValueDisplayed: 2.2uF  [1210_270L]  (hidden comment: GRM32ER72A225KA35L)
C100  VDC_V: 100V  ValueDisplayed: 2.2uF  [1210_270L]  (hidden comment: GRM32ER72A225KA35L)
C101  DNP  [0805_HV]
C102  DNP  [0805_HV]
C103  DNP  [0805_HV]
C104  DNP  [0805_HV]
C105  DNP  [0805_HV]
C106  DNP  [0805_HV]
C107  DNP  [0805_HV]
C108  DNP  [0805_HV]
C109  VDC_V: 50V  ValueDisplayed: 0.01uF  [0603L]  (hidden comment: GRM1885C1H103JA01D)
C110  VDC_V: 50V  ValueDisplayed: 0.01uF  [0603L]  (hidden comment: GRM1885C1H103JA01D)
C111  VDC_V: 50V  ValueDisplayed: 0.01uF  [0603L]  (hidden comment: GRM1885C1H103JA01D)
C112  VDC_V: 50V  ValueDisplayed: 0.01uF  [0603L]  (hidden comment: GRM1885C1H103JA01D)
C113  VDC_V: 50V  ValueDisplayed: 0.01uF  [0603L]  (hidden comment: GRM1885C1H103JA01D)
C114  VDC_V: 50V  ValueDisplayed: 0.01uF  [0603L]  (hidden comment: GRM1885C1H103JA01D)
C115  VDC_V: 50V  ValueDisplayed: 0.01uF  [0603L]  (hidden comment: GRM1885C1H103JA01D)
C116  VDC_V: 50V  ValueDisplayed: 0.01uF  [0603L]  (hidden comment: GRM1885C1H103JA01D)
L6  VAMV1009AA-100MM2  [FP-VAMV1009AA-100MM2_SMT_CMC_9MM2_10MM2-MFG]  (value not drawn)
L7  VAMV1009AA-100MM2  [FP-VAMV1009AA-100MM2_SMT_CMC_9MM2_10MM2-MFG]  (value not drawn)
L8  VAMV1009AA-100MM2  [FP-VAMV1009AA-100MM2_SMT_CMC_9MM2_10MM2-MFG]  (value not drawn)
L9  VAMV1009AA-100MM2  [FP-VAMV1009AA-100MM2_SMT_CMC_9MM2_10MM2-MFG]  (value not drawn)
R32  ValueDisplayed: 10.0k  [0402L]  (hidden comment: CMP-0025958-3)
R33  ValueDisplayed: 10.0k  [0402L]  (hidden comment: CMP-0025958-3)
R34  ValueDisplayed: 10  [0805_HV]  (hidden comment: CRCW080510R0JNEA)
R35  ValueDisplayed: 10.0k  [0402L]  (hidden comment: CMP-0025958-3)
R36  ValueDisplayed: 10.0k  [0402L]  (hidden comment: CMP-0025958-3)
R37  ValueDisplayed: 0  [0402L]  (hidden comment: CRCW04020000Z0ED)
R38  DNP  [0402L]
R39  ValueDisplayed: 10.0k  [0402L]  (hidden comment: CMP-0025958-3)
R40  ValueDisplayed: 10.0k  [0402L]  (hidden comment: CMP-0025958-3)
R41  ValueDisplayed: 0  [0402L]  (hidden comment: CRCW04020000Z0ED)
R42  DNP  ValueDisplayed: 10.0k  [0402L]
R43  ValueDisplayed: 0  [0402L]  (hidden comment: CRCW04020000Z0ED)
R44  ValueDisplayed: 0  [0402L]  (hidden comment: CRCW04020000Z0ED)
R45  ValueDisplayed: 10  [0805_HV]  (hidden comment: CRCW080510R0JNEA)
R46  ValueDisplayed: 10  [0805_HV]  (hidden comment: CRCW080510R0JNEA)
R47  ValueDisplayed: 10  [0805_HV]  (hidden comment: CRCW080510R0JNEA)
R48  ValueDisplayed: 10  [0805_HV]  (hidden comment: CRCW080510R0JNEA)
R49  ValueDisplayed: 10  [0805_HV]  (hidden comment: CRCW080510R0JNEA)
R50  ValueDisplayed: 10  [0805_HV]  (hidden comment: CRCW080510R0JNEA)
R51  ValueDisplayed: 10  [0805_HV]  (hidden comment: CRCW080510R0JNEA)
R53  ValueDisplayed: 0  [1210]  (hidden comment: MCR25JZHJ000)
R54  ValueDisplayed: 0  [1210]  (hidden comment: MCR25JZHJ000)
R55  ValueDisplayed: 0  [1210]  (hidden comment: MCR25JZHJ000)
R56  ValueDisplayed: 0  [1210]  (hidden comment: MCR25JZHJ000)
R57  ValueDisplayed: 0  [1210]  (hidden comment: MCR25JZHJ000)
R58  ValueDisplayed: 0  [1210]  (hidden comment: MCR25JZHJ000)
R59  ValueDisplayed: 0  [1210]  (hidden comment: MCR25JZHJ000)
R60  ValueDisplayed: 0  [1210]  (hidden comment: MCR25JZHJ000)
U2  TAS6584Q1PHD  [QFP64-PHD]

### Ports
FSYNC (in), GPIO_4 (bidir), GPIO_6 (bidir), SCL (bidir), SCLK (in), SDA (bidir), SDIN (in), ~{FAULT2} (out), ~{STBY2} (in)

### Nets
GND: C59.2 C60.2 C61.2 C62.2 C63.2 C64.2 C65.2 C66.2 C67.2 C68.1 C69.1 C70.2 C73.2 C74.2 C75.2 C76.2 C93.2 C94.2 C95.2 C96.2 C97.2 C98.2 C99.2 C100.2 C101.2 C102.2 C103.2 C104.2 C105.2 C106.2 C107.2 C108.2 C109.2 C110.2 C111.2 C112.2 C113.2 C114.2 C115.2 C116.2 R34.2 R38.2 R40.2 R42.1 R43.2 R44.2 R45.2 R46.2 R47.2 R48.2 R49.2 R50.2 R51.2 U2.15(VREG_RET) U2.17(AVDD_RET) U2.18(GVDD_RET) U2.20(GVDD_RET) U2.27(GND) U2.28(GND) U2.29(GND) U2.36(GND) U2.37(GND) U2.44(GND) U2.45(GND) U2.52(GND) U2.53(GND) U2.54(GND)
PVDD: C60.1 C61.1 C62.1 C63.1 C64.1 C65.1 C66.1 C67.1 C73.1 C75.1 U2.22(PVDD_SNS) U2.23(PVDD) U2.24(PVDD) U2.32(PVDD) U2.33(PVDD) U2.40(PVDD) U2.41(PVDD) U2.48(PVDD) U2.49(PVDD) U2.57(PVDD)
VCC: C59.1 R32.2 R33.2 R35.2 R36.2 R37.2 R39.2 U2.4(DVDD_IO)
~{FAULT2}: R35.1 U2.61(~{FAULT}) ; port ~{FAULT2}
~{STBY2}: R33.1 U2.60(~{STBY}) ; port ~{STBY2}
ClassH_tracking: U2.10(GPIO_2)
DVDD_RET2: C71.1 R41.2 R43.1 U2.2(GND)
GPIO_4: R32.1 U2.9(GPIO_1) ; port GPIO_4
GPIO_6: R36.1 U2.62(GPIO_3) ; port GPIO_6
LRCLK: U2.6(FSYNC) ; port FSYNC
SCL: U2.13(SCL) ; port SCL
SCLK: U2.5(SCLK) ; port SCLK
SDA: U2.12(SDA) ; port SDA
SDIN: U2.7(SDIN_1) ; port SDIN
SDOUT1: R40.1 U2.8(SDOUT_1)
SPK_OUT5+: C107.1 C115.1 R59.2
SPK_OUT5-: C108.1 C116.1 R60.2
SPK_OUT6+: C105.1 C113.1 R57.2
SPK_OUT6-: C106.1 C114.1 R58.2
SPK_OUT7+: C103.1 C111.1 R55.2
SPK_OUT7-: C104.1 C112.1 R56.2
SPK_OUT8+: C101.1 C109.1 R53.2
SPK_OUT8-: C102.1 C110.1 R54.2
VBAT: C74.1 C76.1 U2.21(VBAT)
NetC68_2: C68.2 U2.14(VREG_BYP)
NetC69_2: C69.2 U2.16(AVDD_BYP)
NetC70_1: C70.1 U2.19(GVDD_BYP)
NetC71_2: C71.2 C72.2 U2.3(DVDD_BYP) U2.63(PLL_BYP)
NetC72_1: C72.1 R41.1 U2.64(PLL_RET)
NetC77_1: C77.1 C85.2 L6.4(2_Finish) U2.56(OUT_4P)
NetC77_2: C77.2 U2.55(BST_4P)
NetC78_1: C78.1 C86.2 L6.1(1_Start) U2.50(OUT_4M)
NetC78_2: C78.2 U2.51(BST_4M)
NetC79_1: C79.1 C87.2 L7.4(2_Finish) U2.47(OUT_3P)
NetC79_2: C79.2 U2.46(BST_3P)
NetC80_1: C80.1 C88.2 L7.1(1_Start) U2.42(OUT_3M)
NetC80_2: C80.2 U2.43(BST_3M)
NetC81_1: C81.1 C89.2 L8.4(2_Finish) U2.39(OUT_2P)
NetC81_2: C81.2 U2.38(BST_2P)
NetC82_1: C82.1 C90.2 L8.1(1_Start) U2.34(OUT_2M)
NetC82_2: C82.2 U2.35(BST_2M)
NetC83_1: C83.1 C91.2 L9.4(2_Finish) U2.31(OUT_1P)
NetC83_2: C83.2 U2.30(BST_1P)
NetC84_1: C84.1 C92.2 L9.1(1_Start) U2.25(OUT_1M)
NetC84_2: C84.2 U2.26(BST_1M)
NetC85_1: C85.1 R34.1
NetC86_1: C86.1 R45.1
NetC87_1: C87.1 R46.1
NetC88_1: C88.1 R47.1
NetC89_1: C89.1 R48.1
NetC90_1: C90.1 R49.1
NetC91_1: C91.1 R50.1
NetC92_1: C92.1 R51.1
NetC93_1: C93.1 L6.3(2_Start) R53.1
NetC94_1: C94.1 L6.2(1_Finish) R54.1
NetC95_1: C95.1 L7.3(2_Start) R55.1
NetC96_1: C96.1 L7.2(1_Finish) R56.1
NetC97_1: C97.1 L8.3(2_Start) R57.1
NetC98_1: C98.1 L8.2(1_Finish) R58.1
NetC99_1: C99.1 L9.3(2_Start) R59.1
NetC100_1: C100.1 L9.2(1_Finish) R60.1
NetR37_1: R37.1 R38.1 U2.11(I2C_ADDR)
NetR39_1: R39.1 R42.2 U2.59(~{PD})
NetR44_1: R44.1 U2.1(GND)

Not connected (* = marked no-connect by the designer): U2 58(NC) 65(Mounting_Holes)

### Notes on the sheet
- decoupling capacitors, place close to device
- Soft term capacitor
- (near C109) Place 10nF beside connector
- I2S
- I2C
- CONTROL
- GPIO

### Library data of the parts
C59 C68 C69 C71 C72 = CMP-0007139-1: as C1 on sheet TAS6584Q1PHD_1
C60-C63 C75 C76 = CMP-0750040-1: as C2 on sheet TAS6584Q1PHD_1
C64-C67 C73 C74 = CMP-0064935-4: as C6 on sheet TAS6584Q1PHD_1
C70 = CMP-0083622-1: as C12 on sheet TAS6584Q1PHD_1
C77-C84 = CMP-0007145-1: as C19 on sheet TAS6584Q1PHD_1
C85-C92 = CMP-0006707-2: as C27 on sheet TAS6584Q1PHD_1
C93-C100 = CMP-0009232-1: as C35 on sheet TAS6584Q1PHD_1
C101-C108 = CMP-0008022-1: as C43 on sheet TAS6584Q1PHD_1
C109-C116 = CMP-0007174-3: as C51 on sheet TAS6584Q1PHD_1
L6-L9 = CMP-0093075-1: as L2 on sheet TAS6584Q1PHD_1
R32 R33 R35 R36 R39 R40 R42 = CMP-0025958-3: as R2 on sheet TAS6584Q1PHD_1
R34 R45-R51 = CMP-0020448-3: as R16 on sheet TAS6584Q1PHD_1
R37 R41 R43 R44 = CMP-0026822-3: as R9 on sheet TAS6584Q1PHD_1
R38 = CMP-0026822-3: as R8 on sheet TAS6584Q1PHD_1
R53-R60 = CMP-0015361-2: as R24 on sheet TAS6584Q1PHD_1
U2 = TAS6584Q1PHD: as U1 on sheet TAS6584Q1PHD_1

## Sheet PowerSupplies_Boostcontroller.SchDoc: Power Supplies
size Letter; Date: Not shown in title block; ApprovedBy: Not shown in title block; CheckedBy: Not shown in title block; Author: Not shown in title block; CompanyName: Not shown in title block; DrawnBy: LDN; Engineer: Not shown in title block; Organization: Not shown in title block; Address1: Not shown in title block; Address2: Not shown in title block; Address3: Not shown in title block; Address4: Not shown in title block; DocumentNumber: 3; Revision: Use project parameter SCH_Rev; SheetNumber: 3; SheetTotal: 4; PageSetup: Record=PageOptions¦CenterHorizontal=True¦CenterVertical=True¦PrintScale=1.00¦XCorrection=1.00¦YCorrection=1.00¦PrintKind=0¦BorderSize=5000000¦LeftOffset=0¦BottomOffset=0¦Orientation=2¦PaperLength=1000¦PaperWidth=1000¦Scale=100¦PaperSource=15¦PrintQuality=600¦MediaType=1¦DitherType=10¦PaperKind=Letter¦PrintScaleMode=1
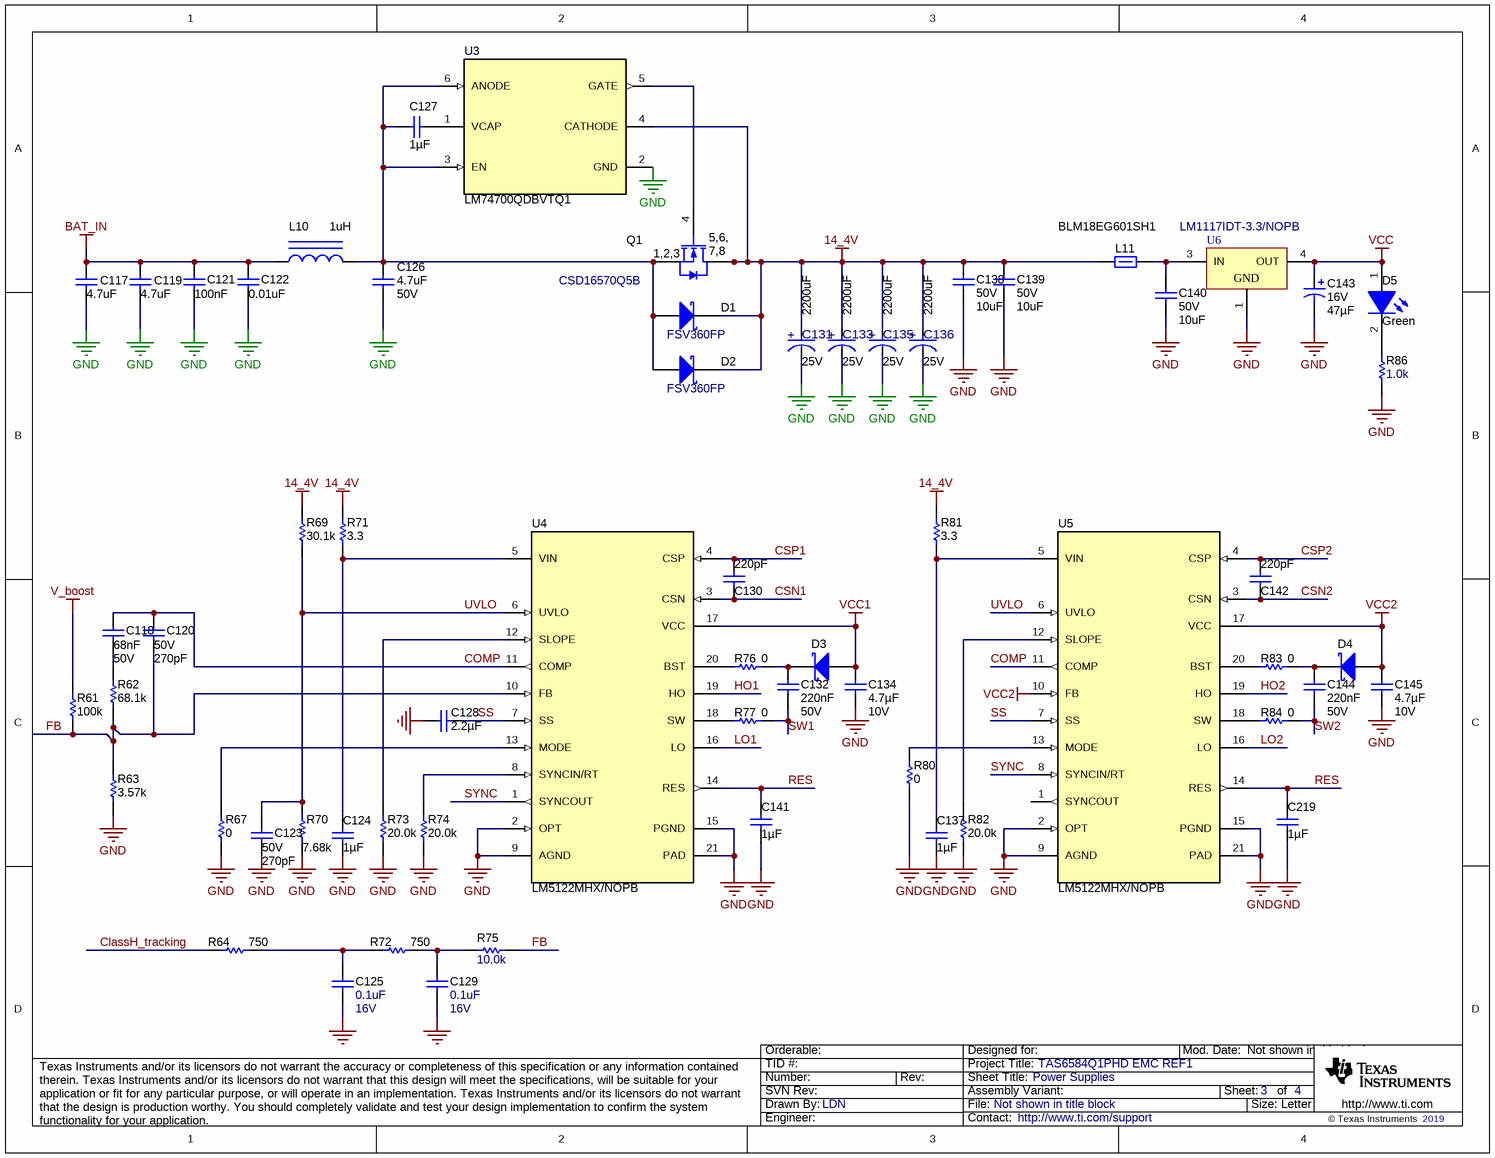
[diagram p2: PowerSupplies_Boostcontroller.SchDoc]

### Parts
C117  ValueDisplayed: 4.7uF  [1210_270L]  (hidden comment: GRM32ER71H475KA88L)
C118  Cap_F: 68nF  VDC_V: 50V  [0603L]  (hidden comment: GRM188R71H683KA93D)
C119  ValueDisplayed: 4.7uF  [1210_270L]  (hidden comment: GRM32ER71H475KA88L)
C120  VDC_V: 50V  ValueDisplayed: 270pF  [0603L]  (hidden comment: GRM1885C1H271JA01D)
C121  Cap_F: 100nF  [0603L]  (hidden comment: GRM188R72A104KA35J)
C122  ValueDisplayed: 0.01uF  [0603L]  (hidden comment: GRM1885C1H103JA01D)
C123  VDC_V: 50V  ValueDisplayed: 270pF  [0603L]  (hidden comment: GRM1885C1H271JA01D)
C124  Cap_F: 1µF  [0603L]  (hidden comment: GCM188R71E105KA64D)
C125  ValueDisplayed: 0.1uF  VDC_V: 16V  [0402L]  (hidden comment: CMP-0006641-2)
C126  VDC_V: 50V  ValueDisplayed: 4.7uF  [1210_270L]  (hidden comment: GRM32ER71H475KA88L)
C127  Cap_F: 1µF  [0603L]  (hidden comment: GCM188R71E105KA64D)
C128  Cap_F: 2.2µF  [0805L]  (hidden comment: GCM21BR71E225KA73L)
C129  ValueDisplayed: 0.1uF  VDC_V: 16V  [0402L]  (hidden comment: CMP-0006641-2)
C130  ValueDisplayed: 220pF  [0402L]  (hidden comment: GRM155R71H221KA01D)
C131  ValueDisplayed: 2200uF  VDC_V: 25V  [FP-UHW1E222MHD_RADIAL-MFG]  (hidden comment: UHW1E222MHD)
C132  Cap_F: 220nF  VDC_V: 50V  [0603L]  (hidden comment: GCM188R71H224KA64D)
C133  ValueDisplayed: 2200uF  VDC_V: 25V  [FP-UHW1E222MHD_RADIAL-MFG]  (hidden comment: UHW1E222MHD)
C134  Cap_F: 4.7µF  VDC_V: 10V  [0603L]  (hidden comment: GRM188Z71A475ME15D)
C135  ValueDisplayed: 2200uF  VDC_V: 25V  [FP-UHW1E222MHD_RADIAL-MFG]  (hidden comment: UHW1E222MHD)
C136  ValueDisplayed: 2200uF  VDC_V: 25V  [FP-UHW1E222MHD_RADIAL-MFG]  (hidden comment: UHW1E222MHD)
C137  Cap_F: 1µF  [0603L]  (hidden comment: GCM188R71E105KA64D)
C138  VDC_V: 50V  ValueDisplayed: 10uF  [1210_270]  (hidden comment: GRM32ER71H106KA12L)
C139  VDC_V: 50V  ValueDisplayed: 10uF  [1210_270]  (hidden comment: GRM32ER71H106KA12L)
C140  VDC_V: 50V  ValueDisplayed: 10uF  [1210_270]  (hidden comment: GRM32ER71H106KA12L)
C141  Cap_F: 1µF  [0603L]  (hidden comment: GCM188R71E105KA64D)
C142  ValueDisplayed: 220pF  [0402L]  (hidden comment: GRM155R71H221KA01D)
C143  VDC_V: 16V  ValueDisplayed: 47µF  [Panasonic_B]  (hidden comment: EEE-FT1C470AR)
C144  Cap_F: 220nF  VDC_V: 50V  [0603L]  (hidden comment: GCM188R71H224KA64D)
C145  Cap_F: 4.7µF  VDC_V: 10V  [0603L]  (hidden comment: GRM188Z71A475ME15D)
C219  Cap_F: 1µF  [0603L]  (hidden comment: GCM188R71E105KA64D)
D1  FSV360FP  [SOD-123HE]
D2  FSV360FP  [SOD-123HE]
D3  PMEG6010CEH,115  [SOD-123F]  (value not drawn)
D4  PMEG6010CEH,115  [SOD-123F]  (value not drawn)
D5  value Green  [LTST-C170KGKT_Green]  (hidden comment: CMP-0002888-1)
L10  ValueDisplayed: 1uH  [SRP1265a]  (hidden comment: SRP1265A-1R0M)
L11  BLM18EG601SH1  [0603L]
Q1  CSD16570Q5B  [DNK0008A]
R61  ValueDisplayed: 100k  [0402L]  (hidden comment: CRCW0402100KFKED)
R62  ValueDisplayed: 68.1k  [0402L]  (hidden comment: CRCW040268K1FKED)
R63  ValueDisplayed: 3.57k  [0402L]  (hidden comment: CRCW04023K57FKED)
R64  ValueDisplayed: 750  [0402L]  (hidden comment: CRCW0402750RFKED)
R67  ValueDisplayed: 0  [0402L]  (hidden comment: 0ohm)
R69  ValueDisplayed: 30.1k  [0402L]  (hidden comment: CRCW040230K1FKED)
R70  ValueDisplayed: 7.68k  [0402L]  (hidden comment: CRCW04027K68FKED)
R71  ValueDisplayed: 3.3  [0603L]  (hidden comment: CRCW06033R30JNEA)
R72  ValueDisplayed: 750  [0402L]  (hidden comment: CRCW0402750RFKED)
R73  ValueDisplayed: 20.0k  [0402L]  (hidden comment: CRCW040220K0FKED)
R74  ValueDisplayed: 20.0k  [0402L]  (hidden comment: CRCW040220K0FKED)
R75  ValueDisplayed: 10.0k  [0402L]  (hidden comment: CMP-0025958-3)
R76  ValueDisplayed: 0  [0402L]  (hidden comment: CRCW04020000Z0ED)
R77  ValueDisplayed: 0  [0402L]  (hidden comment: CRCW04020000Z0ED)
R80  0  [0402L]
R81  ValueDisplayed: 3.3  [0603L]  (hidden comment: CRCW06033R30JNEA)
R82  ValueDisplayed: 20.0k  [0402L]  (hidden comment: CRCW040220K0FKED)
R83  ValueDisplayed: 0  [0402L]  (hidden comment: CRCW04020000Z0ED)
R84  ValueDisplayed: 0  [0402L]  (hidden comment: CRCW04020000Z0ED)
R86  ValueDisplayed: 1.0k  [0402L]  (hidden comment: CRCW04021K00JNED)
U3  LM74700QDBVTQ1  [DBV0006A_N]
U4  LM5122MHX/NOPB  [PWP0020A_N]
U5  LM5122MHX/NOPB  [PWP0020A_N]
U6  LM1117IDT-3.3/NOPB  [NDP0003B_N]

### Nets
14_4V: C131.2(ANODE) C133.2(ANODE) C135.2(ANODE) C136.2(ANODE) C138.1 C139.1 D1.1(K) D2.1(K) L11.1 Q1.5(D) Q1.6(D) Q1.7(D) Q1.8(D) Q1.9(D) R69.2 R71.2 R81.2 U3.4(CATHODE)
BAT_IN: C117.1 C119.1 C121.1 C122.1 L10.1
GND: C117.2 C119.2 C121.2 C122.2 C123.2 C124.2 C125.1 C126.2 C128.2 C129.1 C131.1(CATHODE) C133.1(CATHODE) C134.2 C135.1(CATHODE) C136.1(CATHODE) C137.2 C138.2 C139.2 C140.2 C141.2 C143.2(-) C145.2 C219.2 R63.1 R67.1 R70.1 R73.1 R74.1 R80.1 R82.1 R86.1 U3.2(GND) U4.2(OPT) U4.9(AGND) U4.15(PGND) U4.21(PAD) U5.2(OPT) U5.9(AGND) U5.15(PGND) U5.21(PAD) U6.1(GND)
V_boost: R61.1
VCC: C143.1(+) D5.1(A) U6.4(OUT)
VCC1: C134.1 D3.2(A) U4.17(VCC)
VCC2: C145.1 D4.2(A) U5.10(FB) U5.17(VCC)
ClassH_tracking: R64.1
COMP: C118.1 C120.1 U4.11(COMP) U5.11(COMP)
CSN1: C130.2 U4.3(CSN)
CSN2: C142.2 U5.3(CSN)
CSP1: C130.1 U4.4(CSP)
CSP2: C142.1 U5.4(CSP)
FB: C120.2 R61.2 R62.1 R63.2 R75.1 U4.10(FB)
HO1: U4.19(HO)
HO2: U5.19(HO)
LO1: U4.16(LO)
LO2: U5.16(LO)
RES: C141.1 C219.1 U4.14(RES) U5.14(RES)
SS: C128.1 U4.7(SS) U5.7(SS)
SW1: C132.2 R77.1
SW2: C144.2 R84.1
SYNC: U4.1(SYNCOUT) U5.8(SYNCIN/RT)
UVLO: C123.1 R69.1 R70.2 U4.6(UVLO) U5.6(UVLO)
NetC118_2: C118.2 R62.2
NetC124_1: C124.1 R71.1 U4.5(VIN)
NetC125_2: C125.2 R64.2 R72.1
NetC126_1: C126.1 C127.1 D1.2(A) D2.2(A) L10.2 Q1.1(S) Q1.2(S) Q1.3(S) U3.3(EN) U3.6(ANODE)
NetC127_2: C127.2 U3.1(VCAP)
NetC129_2: C129.2 R72.2 R75.2
NetC132_1: C132.1 D3.1(K) R76.1
NetC137_1: C137.1 R81.1 U5.5(VIN)
NetC140_1: C140.1 L11.2 U6.3(IN)
NetC144_1: C144.1 D4.1(K) R83.1
NetD5_2: D5.2(K) R86.2
NetQ1_4: Q1.4(G) U3.5(GATE)
NetR67_2: R67.2 U4.13(MODE)
NetR73_2: R73.2 U4.12(SLOPE)
NetR74_2: R74.2 U4.8(SYNCIN/RT)
NetR76_2: R76.2 U4.20(BST)
NetR77_2: R77.2 U4.18(SW)
NetR80_2: R80.2 U5.13(MODE)
NetR82_2: R82.2 U5.12(SLOPE)
NetR83_2: R83.2 U5.20(BST)
NetR84_2: R84.2 U5.18(SW)

Not connected (* = marked no-connect by the designer): U5 1(SYNCOUT)

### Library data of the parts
C117 C119 = CMP-0009228-2: CAP, CERM, 4.7 uF, 50 V, +/- 10%, X7R, 1210; Manufacturer: MuRata; TaMin_C: -55°C; ESR_ohm: 2m; Polarized: N; SizeAreaWB_mm2: 14.7; Value1: 0.002 ohm; U/M: EA; Value: 4.7uF; TaMax_C: 125°C; SizeZ_mm: 2.7; SizeX_mm: 3.2; SizeY_mm: 2.5; Cap_Case: 1210; Value2: 50V; SizeArea_mm2: 8; Cap_F: 4.7µF; AEC Category: Q200
C118 = CMP-0007463-1: CAP, CERM, 0.068 uF, 50 V, +/- 10%, X7R, 0603; Manufacturer: MuRata; TaMin_C: -55°C; Polarized: N; SizeAreaWB_mm2: 4.68; Value1: Unknown; U/M: EA; TaMax_C: 125°C; SizeZ_mm: 1; SizeX_mm: 1.6; SizeY_mm: 0.8; Cap_Case: 0603; SizeArea_mm2: 1.28; AEC Category: Q200
C120 C123 = CMP-0007203-1: CAP, CERM, 270 pF, 50 V, +/- 5%, C0G/NP0, 0603; Manufacturer: MuRata; TaMin_C: -55°C; Polarized: N; SizeAreaWB_mm2: 4.68; Value1: Unknown; U/M: EA; Value: 270pF; TaMax_C: 125°C; SizeZ_mm: 1; SizeX_mm: 1.6; SizeY_mm: 0.8; Cap_Case: 0603; SizeArea_mm2: 1.28; AEC Category: Q200
C121 = CMP-0007470-1: CAP, CERM, 0.1 uF, 100 V, +/- 10%, X7R, 0603; Manufacturer: MuRata; TaMin_C: -55°C; Polarized: N; SizeAreaWB_mm2: 4.68; Value1: Unknown; U/M: EA; Value: 0.1uF; TaMax_C: 125°C; SizeZ_mm: 1; SizeX_mm: 1.6; SizeY_mm: 0.8; Cap_Case: 0603; Value2: 100V; SizeArea_mm2: 1.28; AEC Category: Q200
C122 = CMP-0007174-3: CAP, CERM, 0.01 uF, 50 V, +/- 5%, C0G/NP0, 0603; Manufacturer: MuRata; TaMin_C: -55°C; Polarized: N; SizeAreaWB_mm2: 4.68; Value1: Unknown; U/M: EA; Value: 0.01uF; TaMax_C: 125°C; SizeZ_mm: 1; SizeX_mm: 1.6; SizeY_mm: 0.8; Cap_Case: 0603; Value2: 50V; SizeArea_mm2: 1.28; Cap_F: 10nF; AEC Category: Q200
C124 C127 C137 C141 C219 = CMP-0007139-1: as C1 on sheet TAS6584Q1PHD_1
C125 C129 = CMP-0006641-2: CAP, CERM, 0.1 uF, 16 V, +/- 10%, X7R, 0402; PartNumber: GRM155R71C104KA88D; Manufacturer: MuRata; Polarized: N; Value: 0.1uF; U/M: EA; Cap_F: 100nF; Value1: Unknown; TaMin_C: -55°C; TaMax_C: 125°C; Cap_Case: 0402; SizeAreaWB_mm2: 3; SizeZ_mm: 0.6; SizeX_mm: 1; SizeY_mm: 0.5; AEC Category: Q200
C126 = CMP-0009228-2: CAP, CERM, 4.7 uF, 50 V, +/- 10%, X7R, 1210; Manufacturer: MuRata; TaMin_C: -55°C; ESR_ohm: 2m; Polarized: N; SizeAreaWB_mm2: 14.7; Value1: 0.002 ohm; U/M: EA; Value: 4.7uF; TaMax_C: 125°C; SizeZ_mm: 2.7; SizeX_mm: 3.2; SizeY_mm: 2.5; Cap_Case: 1210; SizeArea_mm2: 8; Cap_F: 4.7µF; AEC Category: Q200
C128 = CMP-0083622-1: as C12 on sheet TAS6584Q1PHD_1
C130 C142 = CMP-0006682-1: CAP, CERM, 220 pF, 50 V, +/- 10%, X7R, 0402; Manufacturer: MuRata; TaMin_C: -55°C; Polarized: N; SizeAreaWB_mm2: 3; Value1: Unknown; U/M: EA; Value: 220pF; TaMax_C: 125°C; SizeZ_mm: 0.6; SizeX_mm: 1; SizeY_mm: 0.5; Cap_Case: 0402; Value2: 50V; AEC Category: Q200
C131 C133 C135 C136 = CMP-0093073-1: 2200 µF 25 V Aluminum Electrolytic Capacitors Radial, Can - 10000 Hrs @ 105°C; Manufacturer: Nichicon; Cap_F: 2.2mF; Tolerance_%: 20%; SizeZ_mm: 27mm; Dissipation Factor: 15%; IRMS_A: 3.2A; Leakage Current: 550uA; AEC Qualified: No; Life: 10000Hours; Value: 2.2mF
C132 C144 = CMP-0007145-1: as C19 on sheet TAS6584Q1PHD_1
C134 C145 = CMP-0007498-1: CAP, CERM, 4.7 uF, 10 V, +/- 20%, X7R, 0603; Manufacturer: MuRata; TaMin_C: -55°C; Polarized: N; SizeAreaWB_mm2: 4.68; Value1: Unknown; U/M: EA; Value: 4.7uF; TaMax_C: 125°C; SizeZ_mm: 1; SizeX_mm: 1.6; SizeY_mm: 0.8; Cap_Case: 0603; SizeArea_mm2: 1.28; AEC Category: Q200
C138-C140 = CMP-0009226-3: CAP, CERM, 10 uF, 50 V, +/- 10%, X7R, 1210; Manufacturer: MuRata; TaMin_C: -55°C; Polarized: N; SizeAreaWB_mm2: 14.7; Value1: Unknown; U/M: EA; Value: 10uF; TaMax_C: 125°C; SizeZ_mm: 2.7; SizeX_mm: 3.2; SizeY_mm: 2.5; Cap_Case: 1210; SizeArea_mm2: 8; Cap_F: 10µF; AEC Category: Q200
C143 = CMP-0860542-1: CAP, AL, 47 µF, 16 V, +/- 20%, 0.85 ohm, AEC-Q200 Grade 2, SMD; Manufacturer: Panasonic; AEC Qualified: Y; AEC Grade: 2; U/M: EA; SizeZ_mm: 6.1; ESR_ohm: 0.85; SizeY_mm: 4.3; CompType: Capacitor; TaMax_C: 105°C; TaMin_C: -55°C; IRMS_A: 160mA; SizeArea_mm2: 18.49; Value: 47uF; SizeAreaWB_mm2: 28.09; AEC Category: Q200; Cap_Case: B
D1 D2 = CMP-0028825-2: Diode, Schottky, 60 V, 3 A, AEC-Q101, SOD-123HE; Manufacturer: Fairchild Semiconductor; Vf_V: 650mV; SizeArea_mm2: 6.66; Vr_V: 60V; Green_Lifecycle: Not Set; Value: 60V; Value1: 3A; Green_REACh: Incomplete; SizeY_mm: 1.8; Value2: 0.65V; TJmax_C: 150°C; AEC Category: Q101; SizeAreaWB_mm2: 13.16; SizeZ_mm: 1; AEC Qualified: Y; SizeX_mm: 3.7
D3 D4 = CMP-0028377-1: Diode, Schottky, 60 V, 1 A, SOD-123F; Manufacturer: Nexperia; Io_A: 1A; Green_Lifecycle: Not Set; SizeAreaWB_mm2: 11.7; Vr_V: 60V; Green_REACh: Incomplete; TJmax_C: 150°C; U/M: EA; Value: 60V; SizeZ_mm: 1.1; SizeX_mm: 3.5; SizeY_mm: 1.6; Vf_V: 570mV; Value2: 0.57V; SizeArea_mm2: 5.6; AEC Category: Q101
D5 = CMP-0002888-1: LED, Green, SMD; Manufacturer: Lite-On; PartNumber: LTST-C170KGKT; Type: AlInGaP; Vf_V: 2V; Io_A: 20mA; Value1: W; U/M: EA
L10 = CMP-0056908-1: Inductor, Shielded, 1 uH, 30 A, 0.0017 ohm, AEC-Q200 Grade 0, SMD; Manufacturer: Bourns; Isat: 48A @ 20% inductance drop; Irms: 30A @ 40C rise; Green_Lifecycle: Active; SizeAreaWB_mm2: 224.75; DCR_ohm: 1.7m; Green_REACh: Passed; Value: 1uH; Imax_A: 30A; SizeZ_mm: 6.4; SizeX_mm: 13.5; SizeY_mm: 12.5; SizeArea_mm2: 168.75; Ind_H: 1µH; AEC Qualified: Y; AEC Grade: 0; AEC Category: Q200
L11 = CMP-0003347-2: as L1 on sheet TAS6584Q1PHD_1
Q1 = CMP-0000274-1: MOSFET, N-CH, 25 V, 100 A, DNK0008A (VSON-CLIP-8); Alternate Manufacturer: None; Manufacturer: Texas Instruments; SizeZ_mm: 1; ChType: N; Value2: 192 nC; Value1: 0; VdsMax_V: 25V; SizeX_mm: 6; SizeY_mm: 5; Vgs_V: 20V; Value: 25V; Rdson45_ohm: 800µ; SizeArea_mm2: 30; AEC Category: Q101; IdsMax_A: 100A; SizeAreaWB_mm2: 56; U/M: EA; QgTyp_nC: 192
R61 = CMP-0025950-1: RES, 100 k, 1%, 0.063 W, 0402; Manufacturer: Vishay-Dale; Power_W: 63mW; TempCo: 100 ppm/C; U/M: EA; Value: 100k; EIA_Code: E96; SizeX_mm: 1; SizeY_mm: 0.5; SizeZ_mm: 0.6; Value2: 0.063W; VDC_V: 50V; AEC Category: Q200
R62 = CMP-0026506-1: RES, 68.1 k, 1%, 0.063 W, 0402; Manufacturer: Vishay-Dale; Power_W: 63mW; TempCo: 100 ppm/C; Value_Code: 68k1; U/M: EA; Value: 68.1k; EIA_Code: E96; SizeX_mm: 1; SizeY_mm: 0.5; SizeZ_mm: 0.6; Value2: 0.063W; VDC_V: 50V; AEC Category: Q200
R63 = CMP-0026336-2: RES, 3.57 k, 1%, 0.063 W, AEC-Q200 Grade 0, 0402; Manufacturer: Vishay-Dale; Power_W: 63mW; TempCo: 100 ppm/C; Value_Code: 3k57; Value: 3.57k; EIA_Code: E96; SizeX_mm: 1; SizeY_mm: 0.5; SizeZ_mm: 0.6; Value2: 0.063W; AEC Qualified: Y; VDC_V: 50V; AEC Category: Q200; AEC Grade: 0
R64 R72 = CMP-0026542-2: RES, 750, 1%, 0.063 W, AEC-Q200 Grade 0, 0402; Manufacturer: Vishay-Dale; Power_W: 63mW; TempCo: 100 ppm/C; Value_Code: 750R; Value: 750; EIA_Code: E96; SizeX_mm: 1; SizeY_mm: 0.5; SizeZ_mm: 0.6; Value2: 0.063W; AEC Qualified: Y; VDC_V: 50V; AEC Grade: 0; AEC Category: Q200
R67 = CMP-0026822-3: RES, 0, 5%, 0.063 W, AEC-Q200 Grade 0, 0402; Manufacturer: Vishay-Dale; PartNumber: CRCW04020000Z0ED; Power_W: 63mW; TempCo: 200 ppm/C; Value_Code: 0000; Value: 0; EIA_Code: E24; Res_ohm: DNP; SizeX_mm: 1; SizeY_mm: 0.5; SizeZ_mm: 0.6; Value2: 0.063W; AEC Qualified: Y; VDC_V: 50V; AEC Category: Q200
R69 = CMP-0026284-2: RES, 30.1 k, 1%, 0.063 W, AEC-Q200 Grade 0, 0402; Manufacturer: Vishay-Dale; Power_W: 63mW; TempCo: 100 ppm/C; Value_Code: 30k1; Value: 30.1k; EIA_Code: E96; SizeX_mm: 1; SizeY_mm: 0.5; SizeZ_mm: 0.6; Value2: 0.063W; AEC Qualified: Y; VDC_V: 50V; AEC Category: Q200; AEC Grade: 0
R70 = CMP-0026556-2: RES, 7.68 k, 1%, 0.063 W, AEC-Q200 Grade 0, 0402; Manufacturer: Vishay-Dale; Power_W: 63mW; TempCo: 100 ppm/C; Value_Code: 7k68; Value: 7.68k; EIA_Code: E96; SizeX_mm: 1; SizeY_mm: 0.5; SizeZ_mm: 0.6; Value2: 0.063W; AEC Qualified: Y; VDC_V: 50V; AEC Category: Q200; AEC Grade: 0
R71 R81 = CMP-0025805-4: RES, 3.3, 5%, 0.1 W, AEC-Q200 Grade 0, 0603; Manufacturer: Vishay-Dale; Power_W: 100mW; TempCo: 200 ppm/C; Value_Code: 3R30; Value: 3.3; EIA_Code: E24; SizeX_mm: 1.6; SizeY_mm: 0.8; SizeZ_mm: 1; Value2: 0.1W; SizeArea_mm2: 1.28; AEC Qualified: Y; VDC_V: 75V; AEC Category: Q200; AEC Grade: 0
R73 R74 R82 = CMP-0026162-2: RES, 20.0 k, 1%, 0.063 W, AEC-Q200 Grade 0, 0402; Manufacturer: Vishay-Dale; Power_W: 63mW; TempCo: 100 ppm/C; Value_Code: 20k0; Value: 20.0k; EIA_Code: E96; Res_ohm: 20k; SizeX_mm: 1; SizeY_mm: 0.5; SizeZ_mm: 0.6; Value2: 0.063W; AEC Qualified: Y; VDC_V: 50V; AEC Category: Q200; AEC Grade: 0
R75 = CMP-0025958-3: as R2 on sheet TAS6584Q1PHD_1
R76 R77 R83 R84 = CMP-0026822-3: as R9 on sheet TAS6584Q1PHD_1
R80 = CMP-0026822-3: RES, 0, 5%, 0.063 W, AEC-Q200 Grade 0, 0402; Manufacturer: Vishay-Dale; PartNumber: CRCW04020000Z0ED; Power_W: 63mW; TempCo: 200 ppm/C; Value_Code: 0000; EIA_Code: E24; SizeX_mm: 1; SizeY_mm: 0.5; SizeZ_mm: 0.6; Value2: 0.063W; AEC Qualified: Y; VDC_V: 50V; AEC Category: Q200
R86 = CMP-0026852-3: RES, 1.0 k, 5%, 0.063 W, AEC-Q200 Grade 0, 0402; Manufacturer: Vishay-Dale; Power_W: 63mW; TempCo: 200 ppm/C; Value_Code: 1k00; Value: 1.0k; EIA_Code: E24; Res_ohm: 1k; SizeX_mm: 1; SizeY_mm: 0.5; SizeZ_mm: 0.6; Value2: 0.063W; CompType: Resistor; AEC Qualified: Y; VDC_V: 50V; AEC Category: Q200; AEC Grade: 0
U3 = CMP-0079180-1: Low Iq Always ON Smart Diode Controller, DBV0006A (SOT-23-6); Alternate PartNumber: LM74700QDBVRQ1; Alternate Manufacturer: Texas Instruments; SizeAreaWB_mm2: 14.82; SizeZ_mm: 1.45; SizeX_mm: 2.8; SizeY_mm: 2.9; SizeArea_mm2: 8.12; CompType: IC; AEC Qualified: Y; AEC Category: Q200
U4 U5 = CMP-0066110-1: 3-65V Wide Vin, Current Mode Synchronous Boost Controller with Multiphase Capability, PWP0020A (TSSOP-20); Alternate PartNumber: LM5122MHE/NOPB; Alternate Manufacturer: Texas Instruments; SizeAreaWB_mm2: 71.4; U/M: EA; SizeZ_mm: 1.2; SizeX_mm: 6.4; SizeY_mm: 6.5; SizeArea_mm2: 41.6; CompType: IC
U6 = CMP-0070332-1: 800mA Low-Dropout Linear Regulator, 3-pin TO-252, Pb-Free; Manufacturer: Texas Instruments; CompType: LDO IC; PackageTopMarking: NSUZXYTT*LM1117*IDT-3.3; PowerWise: N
